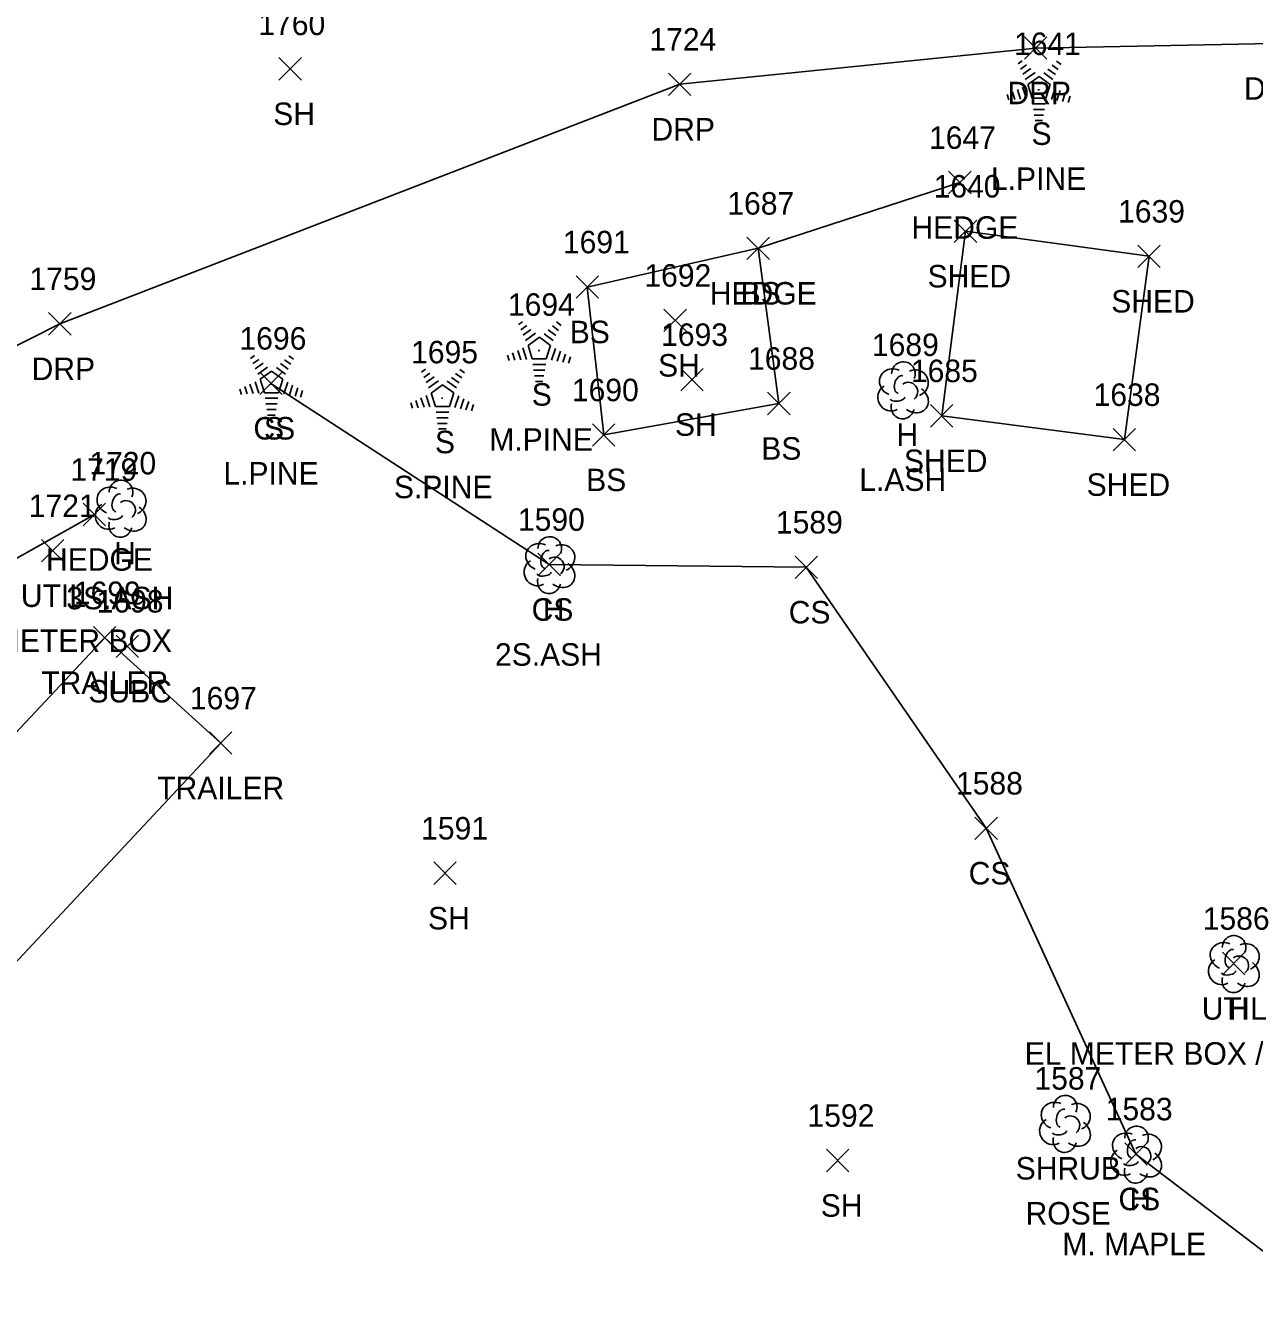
# Model space of a CAD drawing. Extents: x 1477930 to 1480780, y 774090 to 784647.
# Drawn here: x 1479170.3 to 1479279.7, y 774396.6 to 774509.5 of the extents above; entities that cross this region are included whole.
import ezdxf

# ---------------------------------------------------------------- set-up
doc = ezdxf.new("R2010")
doc.units = 0
for name, color, linetype in [('L_A', 7, 'Continuous'), ('L_C', 7, 'Continuous'), ('L_I', 7, 'Continuous'), ('L_TIC', 7, 'Continuous'), ('LAHR', 7, 'Continuous'), ('LBC', 7, 'Continuous'), ('LELB', 7, 'Continuous'), ('LSH', 7, 'Continuous'), ('LTC', 7, 'Continuous'), ('LTD', 7, 'Continuous'), ('R_A', 7, 'Continuous'), ('R_I', 7, 'Continuous'), ('R_TIC', 7, 'Continuous'), ('RDP', 7, 'Continuous'), ('U_A', 7, 'Continuous'), ('U_C', 7, 'Continuous'), ('U_I', 7, 'Continuous'), ('U_TIC', 7, 'Continuous'), ('UDEFAULT', 7, 'Continuous')]:
    doc.layers.add(name, color=color, linetype=linetype)

msp = doc.modelspace()

# ---------------------------------------------------------------- linework, layer by layer
at = {"layer": 'L_TIC'}
for points in [[(1479192.87, 774504.66), (1479194.87, 774506.66)], [(1479194.87, 774504.66), (1479192.87, 774506.66)], [(1479252.44, 774494.54), (1479254.44, 774496.54)], [(1479254.44, 774494.54), (1479252.44, 774496.54)], [(1479252.94, 774490.21), (1479254.94, 774492.21)], [(1479254.94, 774490.21), (1479252.94, 774492.21)], [(1479234.5, 774488.69), (1479236.5, 774490.69)], [(1479236.5, 774488.69), (1479234.5, 774490.69)], [(1479234.5, 774488.69), (1479236.5, 774490.69)], [(1479236.5, 774488.69), (1479234.5, 774490.69)], [(1479269.27, 774487.98), (1479271.27, 774489.98)], [(1479271.27, 774487.98), (1479269.27, 774489.98)], [(1479219.3, 774485.25), (1479221.3, 774487.25)], [(1479221.3, 774485.25), (1479219.3, 774487.25)], [(1479227.12, 774482.28), (1479229.12, 774484.28)], [(1479229.12, 774482.28), (1479227.12, 774484.28)], [(1479191.16, 774476.68), (1479193.16, 774478.68)], [(1479193.16, 774476.68), (1479191.16, 774478.68)], [(1479228.61, 774477.01), (1479230.61, 774479.01)], [(1479230.61, 774477.01), (1479228.61, 774479.01)], [(1479236.34, 774474.89), (1479238.34, 774476.89)], [(1479238.34, 774474.89), (1479236.34, 774476.89)], [(1479250.83, 774473.79), (1479252.83, 774475.79)], [(1479252.83, 774473.79), (1479250.83, 774475.79)], [(1479250.83, 774473.79), (1479252.83, 774475.79)], [(1479252.83, 774473.79), (1479250.83, 774475.79)], [(1479220.76, 774472.09), (1479222.76, 774474.09)], [(1479222.76, 774472.09), (1479220.76, 774474.09)], [(1479267.08, 774471.67), (1479269.08, 774473.67)], [(1479269.08, 774471.67), (1479267.08, 774473.67)], [(1479267.08, 774471.67), (1479269.08, 774473.67)], [(1479269.08, 774471.67), (1479267.08, 774473.67)], [(1479175.45, 774465.01), (1479177.45, 774467.01)], [(1479177.45, 774465.01), (1479175.45, 774467.01)], [(1479215.91, 774460.56), (1479217.91, 774462.56)], [(1479217.91, 774460.56), (1479215.91, 774462.56)], [(1479238.78, 774460.32), (1479240.78, 774462.32)], [(1479240.78, 774460.32), (1479238.78, 774462.32)], [(1479176.37, 774454.05), (1479178.37, 774456.05)], [(1479178.37, 774454.05), (1479176.37, 774456.05)], [(1479186.69, 774444.68), (1479188.69, 774446.68)], [(1479188.69, 774444.68), (1479186.69, 774446.68)], [(1479186.69, 774444.68), (1479188.69, 774446.68)], [(1479188.69, 774444.68), (1479186.69, 774446.68)], [(1479254.79, 774437.1), (1479256.79, 774439.1)], [(1479256.79, 774437.1), (1479254.79, 774439.1)], [(1479206.64, 774433.1), (1479208.64, 774435.1)], [(1479208.64, 774433.1), (1479206.64, 774435.1)], [(1479241.58, 774407.54), (1479243.58, 774409.54)], [(1479243.58, 774407.54), (1479241.58, 774409.54)], [(1479268.11, 774408.12), (1479270.11, 774410.12)], [(1479270.11, 774408.12), (1479268.11, 774410.12)]]:
    msp.add_lwpolyline(points, dxfattribs=at)
at = {"layer": 'LAHR'}
for points in [[(1479253.44, 774495.54), (1479235.5, 774489.69)], [(1479140.96, 774452.11), (1479148.87, 774456.61), (1479164.31, 774459.18), (1479176.45, 774466.01)]]:
    msp.add_lwpolyline(points, dxfattribs=at)
at = {"layer": 'LBC'}
for points in [[(1479268.08, 774472.67), (1479270.27, 774488.98), (1479253.94, 774491.21), (1479251.83, 774474.79)], [(1479268.08, 774472.67), (1479251.83, 774474.79)], [(1479187.69, 774445.68), (1479177.37, 774455.05), (1479151.74, 774427.71), (1479142.55, 774417.77), (1479132.19, 774406.63), (1479142.28, 774397.12)], [(1479187.69, 774445.68), (1479142.28, 774397.12)]]:
    msp.add_lwpolyline(points, dxfattribs=at)
at = {"layer": 'LELB'}
for points in [[(1479235.5, 774489.69), (1479237.34, 774475.89), (1479221.76, 774473.09), (1479220.3, 774486.25)], [(1479220.3, 774486.25), (1479235.5, 774489.69)], [(1479269.11, 774409.12), (1479255.79, 774438.1), (1479239.78, 774461.32), (1479216.91, 774461.56), (1479192.16, 774477.68)], [(1479269.11, 774409.12), (1479302.12, 774383.92)]]:
    msp.add_lwpolyline(points, dxfattribs=at)
at = {"layer": 'LSH'}
msp.add_line((1479262.78, 774411.85), (1479262.78, 774411.85), dxfattribs=at)
msp.add_line((1479262.78, 774411.85), (1479262.78, 774411.85), dxfattribs=at)
msp.add_arc((1479262.82, 774413.29), 1.05, 335.5272, 180.9563, dxfattribs=at)
for centre, major_axis, ratio, start_param, end_param in [((1479261.98, 774412.52), (1.21, -0.51), 0.895232, 1.570796, 4.712389), ((1479263.82, 774412.43), (-1.14, -0.48), 0.949671, 1.570796, 4.712389), ((1479262.57, 774412.31), (-0.208, -0.792), 0.645439, 3.141593, 6.283185), ((1479263.28, 774411.68), (-0.5, 0.667), 0.989748, 3.141593, 6.283185), ((1479261.69, 774411.14), (0.58, -1.04), 0.959034, 3.141593, 6.283185), ((1479263.78, 774411.02), (-1.09, 0.79), 0.841452, 1.570796, 4.712389), ((1479262.78, 774410.35), (0.26, 1.06), 0.942809, 1.570796, 4.712389), ((1479262.32, 774411.1), (-0.625, -0.083), 0.423636, 0, 3.141593)]:
    msp.add_ellipse(centre, major_axis=major_axis, ratio=ratio, start_param=start_param, end_param=end_param, dxfattribs=at)
at = {"layer": 'LTC'}
for p, q in [((1479258.63, 774506.1), (1479258.98, 774506.36)), ((1479262.03, 774506.34), (1479262.45, 774506.03)), ((1479258.84, 774505.63), (1479259.37, 774506.02)), ((1479259.05, 774505.17), (1479259.75, 774505.68)), ((1479259.26, 774504.7), (1479260.13, 774505.34)), ((1479260.91, 774505.29), (1479261.72, 774504.7)), ((1479261.28, 774505.64), (1479261.96, 774505.15)), ((1479261.65, 774505.99), (1479262.2, 774505.59)), ((1479259.48, 774504.25), (1479260.49, 774504.98)), ((1479259.48, 774504.25), (1479259.87, 774503.05)), ((1479260.49, 774504.98), (1479261.49, 774504.26)), ((1479261.49, 774504.26), (1479261.1, 774503.05)), ((1479257.66, 774503.38), (1479257.81, 774502.91)), ((1479258.12, 774503.59), (1479258.33, 774502.94)), ((1479258.57, 774503.81), (1479258.84, 774502.97)), ((1479259.03, 774504.03), (1479259.36, 774503.01)), ((1479261.1, 774503.05), (1479259.87, 774503.05)), ((1479261.93, 774503.98), (1479261.59, 774502.94)), ((1479262.37, 774503.73), (1479262.08, 774502.85)), ((1479262.82, 774503.48), (1479262.58, 774502.75)), ((1479263.26, 774503.23), (1479263.07, 774502.66)), ((1479261.06, 774502.55), (1479259.92, 774502.55)), ((1479260.98, 774502.05), (1479259.99, 774502.05)), ((1479260.89, 774501.55), (1479260.06, 774501.55)), ((1479260.81, 774501.05), (1479260.13, 774501.05)), ((1479214.17, 774482.9), (1479214.53, 774483.16)), ((1479214.38, 774482.43), (1479214.91, 774482.82)), ((1479217.2, 774482.79), (1479217.75, 774482.39)), ((1479217.57, 774483.14), (1479217.99, 774482.83)), ((1479214.59, 774481.97), (1479215.29, 774482.48)), ((1479214.8, 774481.5), (1479215.68, 774482.14)), ((1479215.03, 774481.05), (1479216.04, 774481.78)), ((1479216.04, 774481.78), (1479217.03, 774481.06)), ((1479216.46, 774482.09), (1479217.27, 774481.5)), ((1479216.83, 774482.44), (1479217.51, 774481.95)), ((1479213.66, 774480.39), (1479213.87, 774479.74)), ((1479214.12, 774480.61), (1479214.39, 774479.78)), ((1479214.57, 774480.83), (1479214.9, 774479.81)), ((1479215.03, 774481.05), (1479215.41, 774479.85)), ((1479217.03, 774481.06), (1479216.64, 774479.85)), ((1479217.47, 774480.78), (1479217.13, 774479.75)), ((1479217.92, 774480.53), (1479217.63, 774479.65)), ((1479190.35, 774479.89), (1479190.71, 774480.15)), ((1479190.56, 774479.43), (1479191.09, 774479.81)), ((1479190.77, 774478.96), (1479191.47, 774479.47)), ((1479193.01, 774479.44), (1479193.69, 774478.94)), ((1479193.38, 774479.78), (1479193.93, 774479.38)), ((1479193.75, 774480.13), (1479194.17, 774479.83)), ((1479213.2, 774480.18), (1479213.36, 774479.71)), ((1479216.64, 774479.85), (1479215.41, 774479.85)), ((1479216.6, 774479.35), (1479215.46, 774479.35)), ((1479218.36, 774480.28), (1479218.12, 774479.55)), ((1479218.8, 774480.03), (1479218.62, 774479.46)), ((1479190.98, 774478.49), (1479191.86, 774479.13)), ((1479191.2, 774478.04), (1479192.22, 774478.77)), ((1479192.22, 774478.77), (1479193.21, 774478.05)), ((1479192.64, 774479.09), (1479193.45, 774478.5)), ((1479205.56, 774478.67), (1479205.92, 774478.93)), ((1479205.77, 774478.2), (1479206.3, 774478.59)), ((1479205.98, 774477.74), (1479206.68, 774478.25)), ((1479208.22, 774478.21), (1479208.9, 774477.72)), ((1479208.59, 774478.56), (1479209.14, 774478.16)), ((1479208.96, 774478.91), (1479209.38, 774478.6)), ((1479216.52, 774478.85), (1479215.53, 774478.85)), ((1479216.44, 774478.35), (1479215.61, 774478.35)), ((1479189.38, 774477.17), (1479189.54, 774476.7)), ((1479189.84, 774477.39), (1479190.05, 774476.74)), ((1479190.29, 774477.6), (1479190.57, 774476.77)), ((1479190.75, 774477.82), (1479191.08, 774476.8)), ((1479191.2, 774478.04), (1479191.59, 774476.85)), ((1479193.21, 774478.05), (1479192.82, 774476.85)), ((1479193.65, 774477.78), (1479193.31, 774476.74)), ((1479194.09, 774477.53), (1479193.81, 774476.64)), ((1479194.54, 774477.28), (1479194.3, 774476.55)), ((1479194.98, 774477.03), (1479194.8, 774476.45)), ((1479206.19, 774477.27), (1479207.07, 774477.91)), ((1479206.41, 774476.82), (1479207.43, 774477.55)), ((1479207.43, 774477.55), (1479208.42, 774476.83)), ((1479207.85, 774477.86), (1479208.66, 774477.28)), ((1479216.35, 774477.85), (1479215.68, 774477.85)), ((1479192.82, 774476.85), (1479191.59, 774476.85)), ((1479192.78, 774476.35), (1479191.64, 774476.35)), ((1479192.7, 774475.85), (1479191.71, 774475.85)), ((1479204.59, 774475.95), (1479204.75, 774475.48)), ((1479205.05, 774476.16), (1479205.26, 774475.51)), ((1479205.5, 774476.38), (1479205.78, 774475.55)), ((1479205.96, 774476.6), (1479206.29, 774475.58)), ((1479206.41, 774476.82), (1479206.8, 774475.62)), ((1479208.42, 774476.83), (1479208.03, 774475.62)), ((1479208.86, 774476.56), (1479208.52, 774475.52)), ((1479209.31, 774476.31), (1479209.02, 774475.42)), ((1479209.75, 774476.06), (1479209.51, 774475.33)), ((1479192.62, 774475.35), (1479191.78, 774475.35)), ((1479192.53, 774474.85), (1479191.86, 774474.85)), ((1479208.03, 774475.62), (1479206.8, 774475.62)), ((1479207.99, 774475.12), (1479206.85, 774475.12)), ((1479210.19, 774475.8), (1479210.01, 774475.23)), ((1479207.91, 774474.62), (1479206.92, 774474.62)), ((1479207.83, 774474.12), (1479206.99, 774474.12)), ((1479207.74, 774473.62), (1479207.07, 774473.62))]:
    msp.add_line(p, q, dxfattribs=at)
at = {"layer": 'LTD'}
for p, q in [((1479248.37, 774477.11), (1479248.37, 774477.11)), ((1479248.37, 774477.11), (1479248.37, 774477.11)), ((1479178.78, 774466.58), (1479178.78, 774466.58)), ((1479178.78, 774466.58), (1479178.78, 774466.58)), ((1479216.91, 774461.56), (1479216.91, 774461.56)), ((1479216.91, 774461.56), (1479216.91, 774461.56)), ((1479277.8, 774426.07), (1479277.8, 774426.07)), ((1479277.8, 774426.07), (1479277.8, 774426.07)), ((1479269.11, 774409.12), (1479269.11, 774409.12)), ((1479269.11, 774409.12), (1479269.11, 774409.12))]:
    msp.add_line(p, q, dxfattribs=at)
for centre in [(1479248.42, 774478.54), (1479178.82, 774468.02), (1479216.96, 774462.99), (1479277.84, 774427.5), (1479269.16, 774410.55)]:
    msp.add_arc(centre, 1.05, 335.5272, 180.9563, dxfattribs=at)
for centre, major_axis, ratio, start_param, end_param in [((1479247.58, 774477.77), (1.21, -0.51), 0.895232, 1.570796, 4.712389), ((1479248.16, 774477.57), (-0.208, -0.792), 0.645439, 3.141593, 6.283185), ((1479249.41, 774477.69), (-1.14, -0.48), 0.949671, 1.570796, 4.712389), ((1479247.29, 774476.4), (0.58, -1.04), 0.959034, 3.141593, 6.283185), ((1479248.87, 774476.94), (-0.5, 0.667), 0.989748, 3.141593, 6.283185), ((1479249.37, 774476.27), (-1.09, 0.79), 0.841452, 1.570796, 4.712389), ((1479248.37, 774475.61), (0.26, 1.06), 0.942809, 1.570796, 4.712389), ((1479247.91, 774476.36), (-0.625, -0.083), 0.423636, 0, 3.141593), ((1479177.98, 774467.25), (1.21, -0.51), 0.895232, 1.570796, 4.712389), ((1479178.57, 774467.04), (-0.208, -0.792), 0.645439, 3.141593, 6.283185), ((1479179.82, 774467.17), (-1.14, -0.48), 0.949671, 1.570796, 4.712389), ((1479177.69, 774465.87), (0.58, -1.04), 0.959034, 3.141593, 6.283185), ((1479179.28, 774466.42), (-0.5, 0.667), 0.989748, 3.141593, 6.283185), ((1479178.32, 774465.83), (-0.625, -0.083), 0.423636, 0, 3.141593), ((1479179.78, 774465.75), (-1.09, 0.79), 0.841452, 1.570796, 4.712389), ((1479178.78, 774465.08), (0.26, 1.06), 0.942809, 1.570796, 4.712389), ((1479216.12, 774462.23), (1.21, -0.51), 0.895232, 1.570796, 4.712389), ((1479217.96, 774462.14), (-1.14, -0.48), 0.949671, 1.570796, 4.712389), ((1479216.71, 774462.02), (-0.208, -0.792), 0.645439, 3.141593, 6.283185), ((1479217.41, 774461.39), (-0.5, 0.667), 0.989748, 3.141593, 6.283185), ((1479215.83, 774460.85), (0.58, -1.04), 0.959034, 3.141593, 6.283185), ((1479217.91, 774460.73), (-1.09, 0.79), 0.841452, 1.570796, 4.712389), ((1479216.91, 774460.06), (0.26, 1.06), 0.942809, 1.570796, 4.712389), ((1479216.46, 774460.81), (-0.625, -0.083), 0.423636, 0, 3.141593), ((1479277.01, 774426.73), (1.21, -0.51), 0.895232, 1.570796, 4.712389), ((1479277.59, 774426.52), (-0.208, -0.792), 0.645439, 3.141593, 6.283185), ((1479278.84, 774426.65), (-1.14, -0.48), 0.949671, 1.570796, 4.712389), ((1479276.71, 774425.36), (0.58, -1.04), 0.959034, 3.141593, 6.283185), ((1479278.3, 774425.9), (-0.5, 0.667), 0.989748, 3.141593, 6.283185), ((1479278.8, 774425.23), (-1.09, 0.79), 0.841452, 1.570796, 4.712389), ((1479277.34, 774425.32), (-0.625, -0.083), 0.423636, 0, 3.141593), ((1479277.8, 774424.57), (0.26, 1.06), 0.942809, 1.570796, 4.712389), ((1479268.32, 774409.79), (1.21, -0.51), 0.895232, 1.570796, 4.712389), ((1479268.9, 774409.58), (-0.208, -0.792), 0.645439, 3.141593, 6.283185), ((1479270.15, 774409.7), (-1.14, -0.48), 0.949671, 1.570796, 4.712389), ((1479268.03, 774408.41), (0.58, -1.04), 0.959034, 3.141593, 6.283185), ((1479269.61, 774408.95), (-0.5, 0.667), 0.989748, 3.141593, 6.283185), ((1479270.11, 774408.29), (-1.09, 0.79), 0.841452, 1.570796, 4.712389), ((1479268.65, 774408.37), (-0.625, -0.083), 0.423636, 0, 3.141593), ((1479269.11, 774407.62), (0.26, 1.06), 0.942809, 1.570796, 4.712389)]:
    msp.add_ellipse(centre, major_axis=major_axis, ratio=ratio, start_param=start_param, end_param=end_param, dxfattribs=at)
at = {"layer": 'R_TIC'}
for points in [[(1479259.19, 774506.51), (1479261.19, 774508.51)], [(1479261.19, 774506.51), (1479259.19, 774508.51)], [(1479227.52, 774503.28), (1479229.52, 774505.28)], [(1479229.52, 774503.28), (1479227.52, 774505.28)], [(1479172.38, 774481.97), (1479174.38, 774483.97)], [(1479174.38, 774481.97), (1479172.38, 774483.97)]]:
    msp.add_lwpolyline(points, dxfattribs=at)
at = {"layer": 'RDP'}
msp.add_lwpolyline([(1479362.09, 774490.12), (1479342.05, 774496.54), (1479325.92, 774501.65), (1479312.31, 774505.81), (1479281.23, 774507.91), (1479260.19, 774507.51), (1479228.52, 774504.28), (1479173.38, 774482.97), (1479136.11, 774464.13), (1479110.89, 774453.25), (1479073.73, 774438.02), (1479028.37, 774422.34), (1479014.07, 774419.45), (1479003.41, 774415.12), (1479000.29, 774404.19), (1478987.91, 774394.73), (1478976.96, 774410.39), (1478964.4, 774425.19), (1478951.82, 774441.87), (1478940.93, 774454.02), (1478935.82, 774456.7)], dxfattribs=at)
at = {"layer": 'U_TIC'}
for points in [[(1479178.39, 774453.29), (1479180.39, 774455.29)], [(1479180.39, 774453.29), (1479178.39, 774455.29)]]:
    msp.add_lwpolyline(points, dxfattribs=at)
at = {"layer": 'UDEFAULT'}
for points in [[(1479171.74, 774461.79), (1479173.74, 774463.79)], [(1479173.74, 774461.79), (1479171.74, 774463.79)], [(1479276.8, 774425.07), (1479278.8, 774427.07)], [(1479278.8, 774425.07), (1479276.8, 774427.07)]]:
    msp.add_lwpolyline(points, dxfattribs=at)

# ---------------------------------------------------------------- texts
at = {"layer": 'L_A'}
for s, p in [('SH', (1479192.36, 774500.66)), ('S', (1479259.82, 774498.89)), ('HEDGE', (1479249.14, 774490.54)), ('SHED', (1479250.57, 774486.21)), ('HEDGE', (1479231.2, 774484.69)), ('BS', (1479233.94, 774484.69)), ('SHED', (1479266.91, 774483.98)), ('BS', (1479218.74, 774481.25)), ('SH', (1479226.6, 774478.28)), ('S', (1479215.36, 774475.69)), ('CS', (1479190.6, 774472.68)), ('S', (1479191.54, 774472.68)), ('SH', (1479228.1, 774473.01)), ('H', (1479247.81, 774472.11)), ('S', (1479206.75, 774471.46)), ('BS', (1479235.78, 774470.89)), ('SHED', (1479248.47, 774469.79)), ('SHED', (1479248.47, 774469.79)), ('BS', (1479220.2, 774468.09)), ('SHED', (1479264.72, 774467.67)), ('SHED', (1479264.72, 774467.67)), ('H', (1479178.21, 774461.58)), ('HEDGE', (1479172.15, 774461.01)), ('CS', (1479215.35, 774456.56)), ('H', (1479216.35, 774456.56)), ('CS', (1479238.22, 774456.32)), ('TRAILER', (1479171.73, 774450.05)), ('TRAILER', (1479182.04, 774440.68)), ('TRAILER', (1479182.04, 774440.68)), ('CS', (1479254.23, 774433.1)), ('SH', (1479206.13, 774429.1)), ('H', (1479277.23, 774421.07)), ('SHRUB', (1479258.41, 774406.85)), ('CS', (1479267.55, 774404.12)), ('H', (1479268.54, 774404.12)), ('SH', (1479241.07, 774403.54))]:
    msp.add_text(s, height=2, dxfattribs=at).set_placement(p)
at = {"layer": 'L_C'}
for s, p in [('L.PINE', (1479256.21, 774494.89)), ('M.PINE', (1479211.58, 774471.69)), ('L.PINE', (1479187.93, 774468.68)), ('S.PINE', (1479203.1, 774467.46)), ('L.ASH', (1479244.5, 774468.11)), ('3S.ASH', (1479173.96, 774457.58)), ('2S.ASH', (1479212.09, 774452.56)), ('ROSE', (1479259.29, 774402.85)), ('M. MAPLE', (1479262.56, 774400.12))]:
    msp.add_text(s, height=2, dxfattribs=at).set_placement(p)
at = {"layer": 'L_I'}
for s, p in [('1760', (1479191.04, 774508.66)), ('1641', (1479258.26, 774506.89)), ('1647', (1479250.7, 774498.54)), ('1640', (1479251.11, 774494.21)), ('1687', (1479232.76, 774492.69)), ('1687', (1479232.76, 774492.69)), ('1639', (1479267.52, 774491.98)), ('1691', (1479218.13, 774489.25)), ('1692', (1479225.38, 774486.28)), ('1694', (1479213.24, 774483.69)), ('1696', (1479189.36, 774480.68)), ('1696', (1479189.36, 774480.68)), ('1693', (1479226.87, 774481.01)), ('1695', (1479204.63, 774479.46)), ('1689', (1479245.62, 774480.11)), ('1688', (1479234.6, 774478.89)), ('1685', (1479249.09, 774477.79)), ('1685', (1479249.09, 774477.79)), ('1690', (1479218.93, 774476.09)), ('1638', (1479265.34, 774475.67)), ('1638', (1479265.34, 774475.67)), ('1720', (1479176, 774469.58)), ('1719', (1479174.32, 774469.01)), ('1590', (1479214.13, 774464.56)), ('1590', (1479214.13, 774464.56)), ('1589', (1479237.08, 774464.32)), ('1699', (1479174.63, 774458.05)), ('1697', (1479184.95, 774448.68)), ('1697', (1479184.95, 774448.68)), ('1588', (1479253.1, 774441.1)), ('1591', (1479205.52, 774437.1)), ('1586', (1479275.05, 774429.07)), ('1587', (1479260.08, 774414.85)), ('1583', (1479266.42, 774412.12)), ('1583', (1479266.42, 774412.12)), ('1592', (1479239.89, 774411.54))]:
    msp.add_text(s, height=2, dxfattribs=at).set_placement(p)
at = {"layer": 'LTC'}
for p in [(1479260.38, 774503.99), (1479215.92, 774480.79), (1479192.1, 774477.79), (1479207.31, 774476.56)]:
    msp.add_text('.', height=1.04, rotation=270, dxfattribs=at).set_placement(p)
at = {"layer": 'R_A'}
for p in [(1479257.68, 774502.51), (1479278.72, 774502.91), (1479226.01, 774499.28), (1479170.87, 774477.97)]:
    msp.add_text('DRP', height=2, dxfattribs=at).set_placement(p)
at = {"layer": 'R_I'}
for s, p in [('1724', (1479225.83, 774507.28)), ('1759', (1479170.68, 774485.97))]:
    msp.add_text(s, height=2, dxfattribs=at).set_placement(p)
at = {"layer": 'U_A'}
for s, p in [('UTIL', (1479169.91, 774457.79)), ('SUBC', (1479175.92, 774449.29)), ('UTIL', (1479274.96, 774421.07))]:
    msp.add_text(s, height=2, dxfattribs=at).set_placement(p)
at = {"layer": 'U_C'}
for s, p in [('ELEC METER BOX', (1479159.87, 774453.79)), ('EL METER BOX / SHRUB', (1479259.21, 774417.07))]:
    msp.add_text(s, height=2, dxfattribs=at).set_placement(p)
at = {"layer": 'U_I'}
for s, p in [('1721', (1479170.62, 774465.79)), ('1698', (1479176.65, 774457.29)), ('1586', (1479275.05, 774429.07))]:
    msp.add_text(s, height=2, dxfattribs=at).set_placement(p)

doc.saveas('drawing.dxf')
